(* Logix 5000 project; controller AMCI_3601_AOP_AOI_Sample_RSLogix_V28 vendor 1 type 14 code 108 rev 28.11; software revision 28.00; part 2 of 4 *)

ADD_ON_INSTRUCTION AMCI_3601_AOP_Immediate_Stop   (* revision 0.0, vendor AMCI, ExecuteEnableInFalse *)
// Revision note:
// 3/2020: Version 0 is the initial release
VAR_INPUT
   Axis_Status_Bits : INT; {required}
END_VAR
VAR_OUTPUT
   EN : BOOL; {access Read Only, visible}
   ER : BOOL; {access Read Only, visible}
END_VAR
VAR_IN_OUT
   AMCI_3601_output_data : AM:1769_3601:O:0; {required}
END_VAR
VAR
   Upper_Result_X_1000 : DINT;
   command_data_block : INT[10];
        [1]   // Command Bits LSW
        [3]   // Lower Target Position
        [5]   // Lower Programmed Speed
        [0]   // Command Bits MSW
        [2]   // Upper Target Position
        [4]   // Upper Programmed Speed
END_VAR

ROUTINE EnableInFalse   (* ladder *)
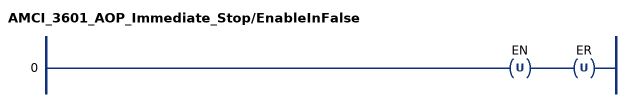
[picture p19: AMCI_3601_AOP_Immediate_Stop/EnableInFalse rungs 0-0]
   0: OTU(EN)OTU(ER);
END_ROUTINE

ROUTINE Logic   (* ladder *)
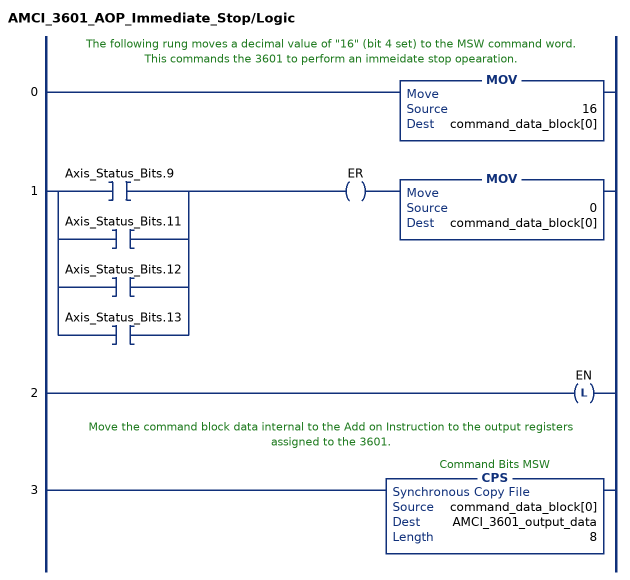
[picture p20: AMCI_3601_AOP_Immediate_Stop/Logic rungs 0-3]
   // The following rung moves a decimal value of "16" (bit 4 set) to the MSW command word.  This commands the 3601 to perform an immeidate stop opearation.
   0: MOV(16,command_data_block[0]);
   1: [XIC(Axis_Status_Bits.9) ,XIC(Axis_Status_Bits.11) ,XIC(Axis_Status_Bits.12) ,XIC(Axis_Status_Bits.13) ]OTE(ER)MOV(0,command_data_block[0]);
   2: OTL(EN);
   // Move the command block data internal to the Add on Instruction to the output registers assigned to the 3601.
   3: CPS(command_data_block[0],AMCI_3601_output_data,8);
END_ROUTINE
END_ADD_ON_INSTRUCTION

ADD_ON_INSTRUCTION AMCI_3601_AOP_Manual_Move_CCW   (* revision 0.0, vendor AMCI, ExecuteEnableInFalse *)
// Revision note:
// 3/2020: Version 0 is the initial release
VAR_INPUT
   Axis_Status_Bits : INT; {required}
   _0_normal_1_S_Curve_Acceleration : BOOL;
   _0_Triangular_1_Trapezoidal_S_Curve : BOOL;
   Programmed_Speed : DINT; {required}
   Acceleration : INT; {required}
   Deceleration : INT; {required}
END_VAR
VAR_OUTPUT
   EN : BOOL; {access Read Only, visible}
   Manual_Move_CCW_Occurring : BOOL; {access Read Only, visible}
   ER : BOOL; {access Read Only, visible}
END_VAR
VAR_IN_OUT
   AMCI_3601_output_data : AM:1769_3601:O:0; {required}
END_VAR
VAR
   Upper_Result_X_1000 : DINT;
   command_data_block : INT[10];
        [1]   // Command Bits LSW
        [3]   // Lower Target Position
        [5]   // Lower Programmed Speed
        [0]   // Command Bits MSW
        [2]   // Upper Target Position
        [4]   // Upper Programmed Speed
END_VAR

ROUTINE EnableInFalse   (* ladder *)
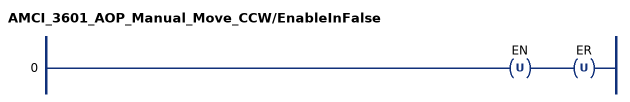
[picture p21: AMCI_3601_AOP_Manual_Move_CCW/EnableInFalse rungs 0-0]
   0: OTU(EN)OTU(ER);
END_ROUTINE

ROUTINE Logic   (* ladder *)
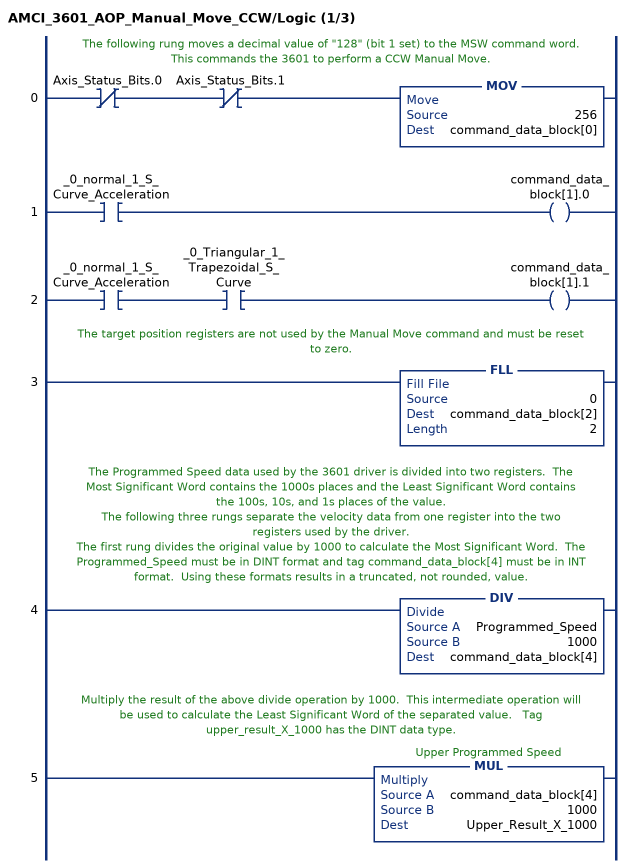
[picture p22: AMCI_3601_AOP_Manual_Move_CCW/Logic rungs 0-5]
   // The following rung moves a decimal value of "128" (bit 1 set) to the MSW command word.  This commands the 3601 to perform a CCW Manual Move.
   0: XIO(Axis_Status_Bits.0)XIO(Axis_Status_Bits.1)MOV(256,command_data_block[0]);
   1: XIC(_0_normal_1_S_Curve_Acceleration)OTE(command_data_block[1].0);
   2: XIC(_0_normal_1_S_Curve_Acceleration)XIC(_0_Triangular_1_Trapezoidal_S_Curve)OTE(command_data_block[1].1);
   // The target position registers are not used by the Manual Move command and must be reset to zero.
   3: FLL(0,command_data_block[2],2);
   // The Programmed Speed data used by the 3601 driver is divided into two registers.  The Most Significant Word contains the 1000s places and the Least Significant Word contains the 100s, 10s, and 1s places of the value.
   // The following three rungs separate the velocity data from one register into the two registers used by the driver.
   // The first rung divides the original value by 1000 to calculate the Most Significant Word.  The Programmed_Speed must be in DINT format and tag command_data_block[4] must be in INT format.  Using these formats results in a truncated, not rounded, value.
   4: DIV(Programmed_Speed,1000,command_data_block[4]);
   // Multiply the result of the above divide operation by 1000.  This intermediate operation will be used to calculate the Least Significant Word of the separated value.   Tag upper_result_X_1000 has the DINT data type.
   5: MUL(command_data_block[4],1000,Upper_Result_X_1000);
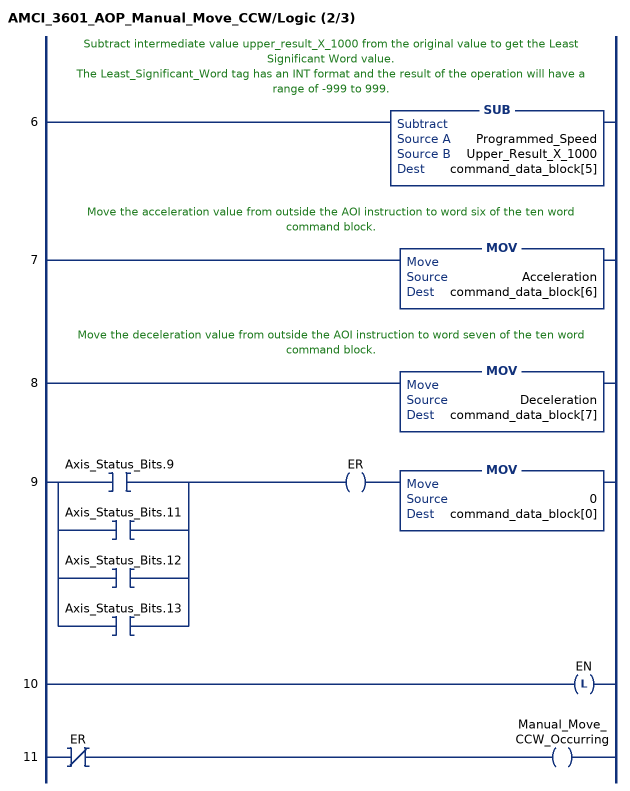
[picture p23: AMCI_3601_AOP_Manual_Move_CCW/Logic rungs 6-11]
   // Subtract intermediate value upper_result_X_1000 from the original value to get the Least Significant Word value.
   // The Least_Significant_Word tag has an INT format and the result of the operation will have a range of -999 to 999.
   6: SUB(Programmed_Speed,Upper_Result_X_1000,command_data_block[5]);
   // Move the acceleration value from outside the AOI instruction to word six of the ten word command block.
   7: MOV(Acceleration,command_data_block[6]);
   // Move the deceleration value from outside the AOI instruction to word seven of the ten word command block.
   8: MOV(Deceleration,command_data_block[7]);
   9: [XIC(Axis_Status_Bits.9) ,XIC(Axis_Status_Bits.11) ,XIC(Axis_Status_Bits.12) ,XIC(Axis_Status_Bits.13) ]OTE(ER)MOV(0,command_data_block[0]);
   10: OTL(EN);
   11: XIO(ER)OTE(Manual_Move_CCW_Occurring);
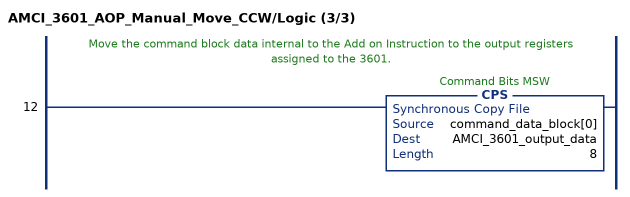
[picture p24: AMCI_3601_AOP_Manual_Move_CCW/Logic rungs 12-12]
   // Move the command block data internal to the Add on Instruction to the output registers assigned to the 3601.
   12: CPS(command_data_block[0],AMCI_3601_output_data,8);
END_ROUTINE
END_ADD_ON_INSTRUCTION

ADD_ON_INSTRUCTION AMCI_3601_AOP_Manual_Move_CW   (* revision 0.0, vendor AMCI, ExecuteEnableInFalse *)
// Revision note:
// 3/2020: Version 0 is the initial release
VAR_INPUT
   Axis_Status_Bits : INT; {required}
   _0_normal_1_S_Curve_Acceleration : BOOL;
   _0_Triangular_1_Trapezoidal_S_Curve : BOOL;
   Programmed_Speed : DINT; {required}
   Acceleration : INT; {required}
   Deceleration : INT; {required}
END_VAR
VAR_OUTPUT
   EN : BOOL; {access Read Only, visible}
   Manual_Move_CW_Occurring : BOOL; {access Read Only, visible}
   ER : BOOL; {access Read Only, visible}
END_VAR
VAR_IN_OUT
   AMCI_3601_output_data : AM:1769_3601:O:0; {required}
END_VAR
VAR
   Upper_Result_X_1000 : DINT;
   command_data_block : INT[10];
        [1]   // Command Bits LSW
        [3]   // Lower Target Position
        [5]   // Lower Programmed Speed
        [0]   // Command Bits MSW
        [2]   // Upper Target Position
        [4]   // Upper Programmed Speed
END_VAR

ROUTINE EnableInFalse   (* ladder *)
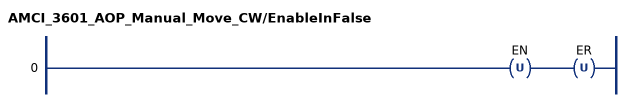
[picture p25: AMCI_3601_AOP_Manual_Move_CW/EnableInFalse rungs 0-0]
   0: OTU(EN)OTU(ER);
END_ROUTINE

ROUTINE Logic   (* ladder *)
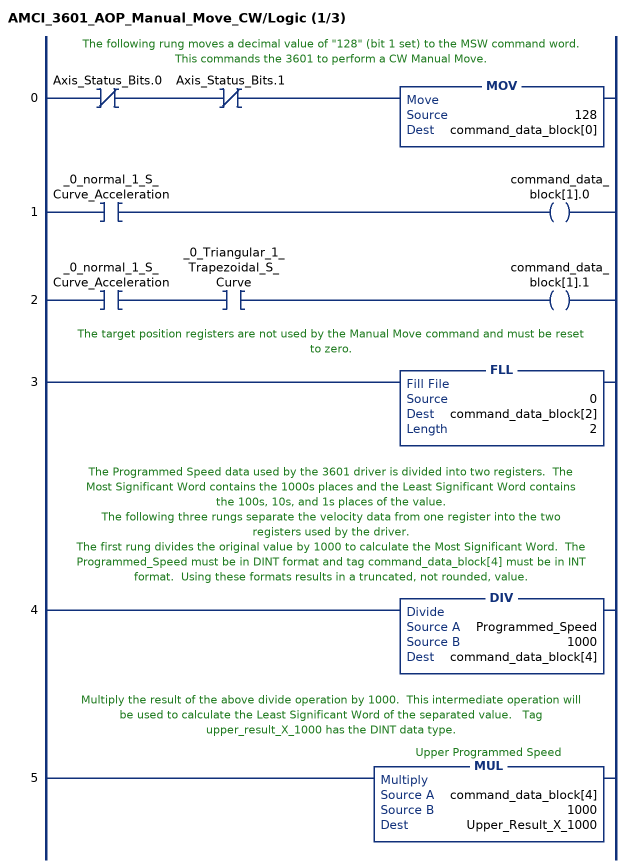
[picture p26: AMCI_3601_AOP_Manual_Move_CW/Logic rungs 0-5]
   // The following rung moves a decimal value of "128" (bit 1 set) to the MSW command word.  This commands the 3601 to perform a CW Manual Move.
   0: XIO(Axis_Status_Bits.0)XIO(Axis_Status_Bits.1)MOV(128,command_data_block[0]);
   1: XIC(_0_normal_1_S_Curve_Acceleration)OTE(command_data_block[1].0);
   2: XIC(_0_normal_1_S_Curve_Acceleration)XIC(_0_Triangular_1_Trapezoidal_S_Curve)OTE(command_data_block[1].1);
   // The target position registers are not used by the Manual Move command and must be reset to zero.
   3: FLL(0,command_data_block[2],2);
   // The Programmed Speed data used by the 3601 driver is divided into two registers.  The Most Significant Word contains the 1000s places and the Least Significant Word contains the 100s, 10s, and 1s places of the value.
   // The following three rungs separate the velocity data from one register into the two registers used by the driver.
   // The first rung divides the original value by 1000 to calculate the Most Significant Word.  The Programmed_Speed must be in DINT format and tag command_data_block[4] must be in INT format.  Using these formats results in a truncated, not rounded, value.
   4: DIV(Programmed_Speed,1000,command_data_block[4]);
   // Multiply the result of the above divide operation by 1000.  This intermediate operation will be used to calculate the Least Significant Word of the separated value.   Tag upper_result_X_1000 has the DINT data type.
   5: MUL(command_data_block[4],1000,Upper_Result_X_1000);
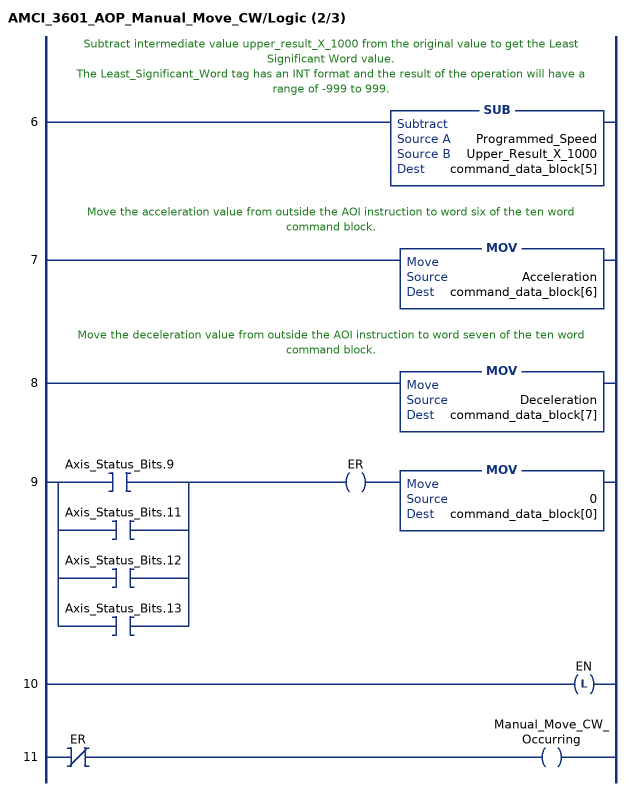
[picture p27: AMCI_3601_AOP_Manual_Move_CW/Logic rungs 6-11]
   // Subtract intermediate value upper_result_X_1000 from the original value to get the Least Significant Word value.
   // The Least_Significant_Word tag has an INT format and the result of the operation will have a range of -999 to 999.
   6: SUB(Programmed_Speed,Upper_Result_X_1000,command_data_block[5]);
   // Move the acceleration value from outside the AOI instruction to word six of the ten word command block.
   7: MOV(Acceleration,command_data_block[6]);
   // Move the deceleration value from outside the AOI instruction to word seven of the ten word command block.
   8: MOV(Deceleration,command_data_block[7]);
   9: [XIC(Axis_Status_Bits.9) ,XIC(Axis_Status_Bits.11) ,XIC(Axis_Status_Bits.12) ,XIC(Axis_Status_Bits.13) ]OTE(ER)MOV(0,command_data_block[0]);
   10: OTL(EN);
   11: XIO(ER)OTE(Manual_Move_CW_Occurring);
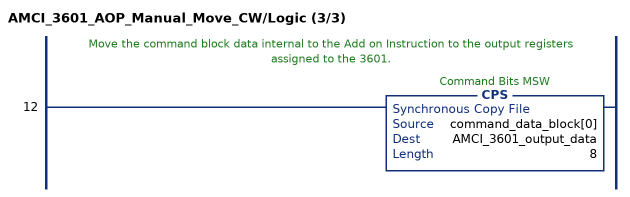
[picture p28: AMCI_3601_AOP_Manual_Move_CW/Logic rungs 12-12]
   // Move the command block data internal to the Add on Instruction to the output registers assigned to the 3601.
   12: CPS(command_data_block[0],AMCI_3601_output_data,8);
END_ROUTINE
END_ADD_ON_INSTRUCTION

ADD_ON_INSTRUCTION AMCI_3601_AOP_Min_Registration_Distance   (* revision 0.0, vendor AMCI, ExecuteEnableInFalse *)
// Revision note:
// 3/2020: Version 0 is the initial release
VAR_INPUT
   Axis_Status_Bits : INT; {required}
   Target_Position : DINT; {required}
END_VAR
VAR_OUTPUT
   EN : BOOL; {access Read Only, visible}
   ER : BOOL; {access Read Only, visible}
END_VAR
VAR_IN_OUT
   AMCI_3601_output_data : AM:1769_3601:O:0; {required}
END_VAR
VAR
   Upper_Result_X_1000 : DINT;
   command_data_block : INT[10];
        [1]   // Command Bits LSW
        [3]   // Lower Target Position
        [5]   // Lower Programmed Speed
        [0]   // Command Bits MSW
        [2]   // Upper Target Position
        [4]   // Upper Programmed Speed
END_VAR

ROUTINE EnableInFalse   (* ladder *)
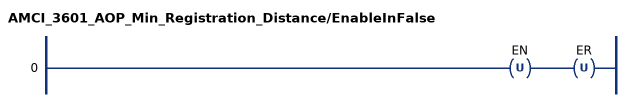
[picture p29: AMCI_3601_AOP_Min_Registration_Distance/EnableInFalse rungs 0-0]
   0: OTU(EN)OTU(ER);
END_ROUTINE

ROUTINE Logic   (* ladder *)
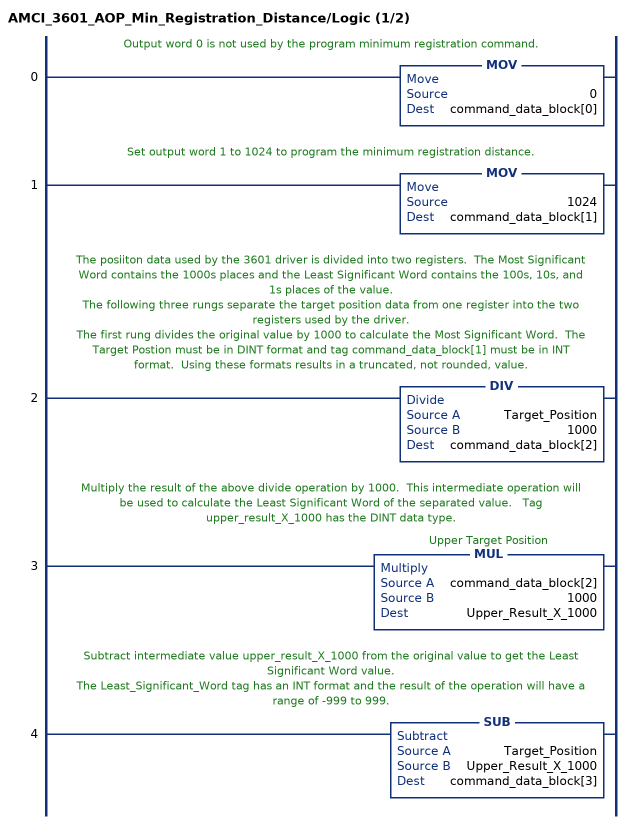
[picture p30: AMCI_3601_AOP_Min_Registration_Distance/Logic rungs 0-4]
   // Output word 0 is not used by the program minimum registration command.
   0: MOV(0,command_data_block[0]);
   // Set output word 1 to 1024 to program the minimum registration distance.
   1: MOV(1024,command_data_block[1]);
   // The posiiton data used by the 3601 driver is divided into two registers.  The Most Significant Word contains the 1000s places and the Least Significant Word contains the 100s, 10s, and 1s places of the value.
   // The following three rungs separate the target position data from one register into the two registers used by the driver.
   // The first rung divides the original value by 1000 to calculate the Most Significant Word.  The Target Postion must be in DINT format and tag command_data_block[1] must be in INT format.  Using these formats results in a truncated, not rounded, value.
   2: DIV(Target_Position,1000,command_data_block[2]);
   // Multiply the result of the above divide operation by 1000.  This intermediate operation will be used to calculate the Least Significant Word of the separated value.   Tag upper_result_X_1000 has the DINT data type.
   3: MUL(command_data_block[2],1000,Upper_Result_X_1000);
   // Subtract intermediate value upper_result_X_1000 from the original value to get the Least Significant Word value.
   // The Least_Significant_Word tag has an INT format and the result of the operation will have a range of -999 to 999.
   4: SUB(Target_Position,Upper_Result_X_1000,command_data_block[3]);
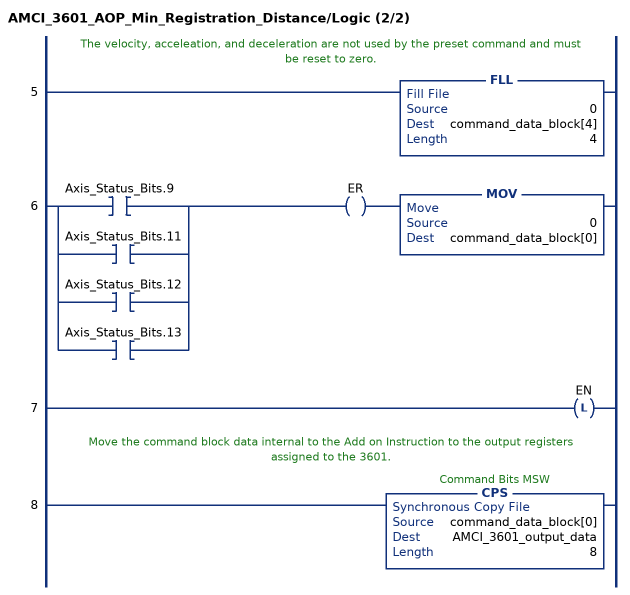
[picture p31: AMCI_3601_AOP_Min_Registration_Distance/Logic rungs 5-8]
   // The velocity, acceleation, and deceleration are not used by the preset command and must be reset to zero.
   5: FLL(0,command_data_block[4],4);
   6: [XIC(Axis_Status_Bits.9) ,XIC(Axis_Status_Bits.11) ,XIC(Axis_Status_Bits.12) ,XIC(Axis_Status_Bits.13) ]OTE(ER)MOV(0,command_data_block[0]);
   7: OTL(EN);
   // Move the command block data internal to the Add on Instruction to the output registers assigned to the 3601.
   8: CPS(command_data_block[0],AMCI_3601_output_data,8);
END_ROUTINE
END_ADD_ON_INSTRUCTION

ADD_ON_INSTRUCTION AMCI_3601_AOP_Preset   (* revision 0.0, vendor AMCI, ExecuteEnableInFalse *)
// Revision note:
// 3/2020: Version 0 is the initial release
VAR_INPUT
   Axis_Status_Bits : INT; {required}
   Target_Position : DINT; {required}
END_VAR
VAR_OUTPUT
   EN : BOOL; {access Read Only, visible}
   ER : BOOL; {access Read Only, visible}
END_VAR
VAR_IN_OUT
   AMCI_3601_output_data : AM:1769_3601:O:0; {required}
END_VAR
VAR
   Upper_Result_X_1000 : DINT;
   command_data_block : INT[10];
        [1]   // Command Bits LSW
        [3]   // Lower Target Position
        [5]   // Lower Programmed Speed
        [0]   // Command Bits MSW
        [2]   // Upper Target Position
        [4]   // Upper Programmed Speed
END_VAR

ROUTINE EnableInFalse   (* ladder *)
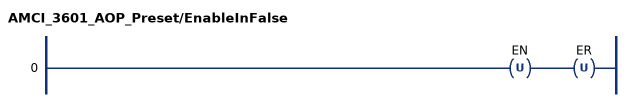
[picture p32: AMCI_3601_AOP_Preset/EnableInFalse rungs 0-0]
   0: OTU(EN)OTU(ER);
END_ROUTINE

ROUTINE Logic   (* ladder *)
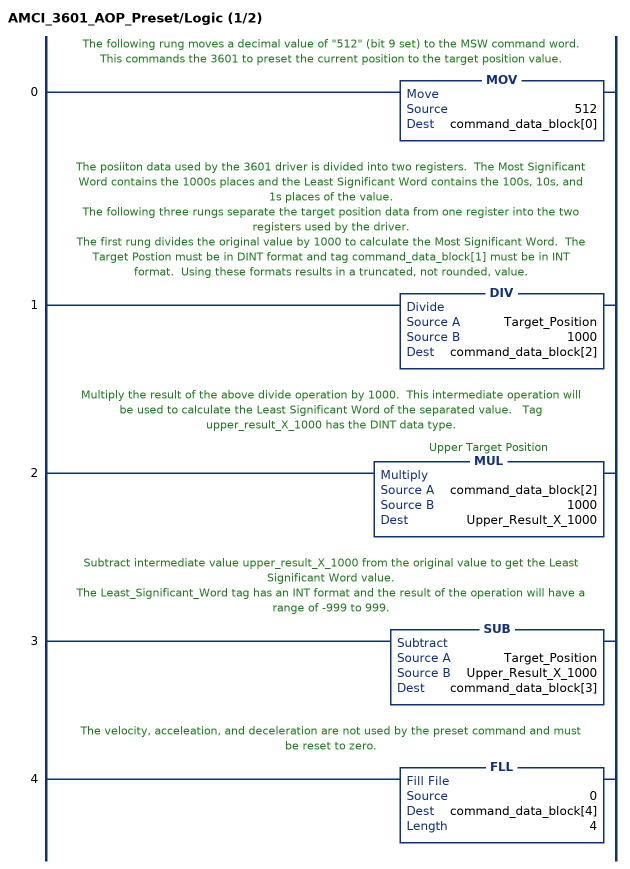
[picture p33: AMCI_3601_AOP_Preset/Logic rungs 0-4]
   // The following rung moves a decimal value of "512" (bit 9 set) to the MSW command word.  This commands the 3601 to preset the current position to the target position value.
   0: MOV(512,command_data_block[0]);
   // The posiiton data used by the 3601 driver is divided into two registers.  The Most Significant Word contains the 1000s places and the Least Significant Word contains the 100s, 10s, and 1s places of the value.
   // The following three rungs separate the target position data from one register into the two registers used by the driver.
   // The first rung divides the original value by 1000 to calculate the Most Significant Word.  The Target Postion must be in DINT format and tag command_data_block[1] must be in INT format.  Using these formats results in a truncated, not rounded, value.
   1: DIV(Target_Position,1000,command_data_block[2]);
   // Multiply the result of the above divide operation by 1000.  This intermediate operation will be used to calculate the Least Significant Word of the separated value.   Tag upper_result_X_1000 has the DINT data type.
   2: MUL(command_data_block[2],1000,Upper_Result_X_1000);
   // Subtract intermediate value upper_result_X_1000 from the original value to get the Least Significant Word value.
   // The Least_Significant_Word tag has an INT format and the result of the operation will have a range of -999 to 999.
   3: SUB(Target_Position,Upper_Result_X_1000,command_data_block[3]);
   // The velocity, acceleation, and deceleration are not used by the preset command and must be reset to zero.
   4: FLL(0,command_data_block[4],4);
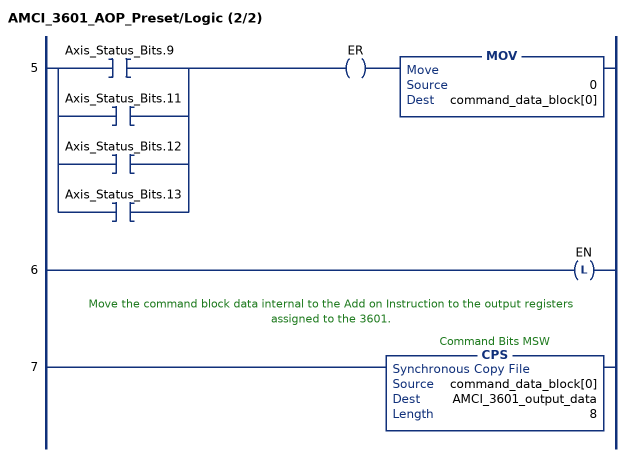
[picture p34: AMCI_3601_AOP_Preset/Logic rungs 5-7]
   5: [XIC(Axis_Status_Bits.9) ,XIC(Axis_Status_Bits.11) ,XIC(Axis_Status_Bits.12) ,XIC(Axis_Status_Bits.13) ]OTE(ER)MOV(0,command_data_block[0]);
   6: OTL(EN);
   // Move the command block data internal to the Add on Instruction to the output registers assigned to the 3601.
   7: CPS(command_data_block[0],AMCI_3601_output_data,8);
END_ROUTINE
END_ADD_ON_INSTRUCTION

ADD_ON_INSTRUCTION AMCI_3601_AOP_Preset_Encoder   (* revision 0.0, vendor AMCI, ExecuteEnableInFalse *)
// Revision note:
// 3/2020: Version 0 is the initial release
VAR_INPUT
   Axis_Status_Bits : INT; {required}
   Target_Position : DINT; {required}
END_VAR
VAR_OUTPUT
   EN : BOOL; {access Read Only, visible}
   ER : BOOL; {access Read Only, visible}
END_VAR
VAR_IN_OUT
   AMCI_3601_output_data : AM:1769_3601:O:0; {required}
END_VAR
VAR
   Upper_Result_X_1000 : DINT;
   command_data_block : INT[10];
        [1]   // Command Bits LSW
        [3]   // Lower Target Position
        [5]   // Lower Programmed Speed
        [0]   // Command Bits MSW
        [2]   // Upper Target Position
        [4]   // Upper Programmed Speed
END_VAR

ROUTINE EnableInFalse   (* ladder *)
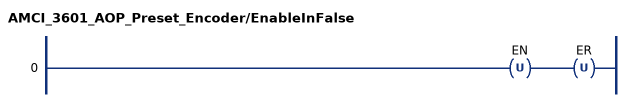
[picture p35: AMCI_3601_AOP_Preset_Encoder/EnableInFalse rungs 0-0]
   0: OTU(EN)OTU(ER);
END_ROUTINE

ROUTINE Logic   (* ladder *)
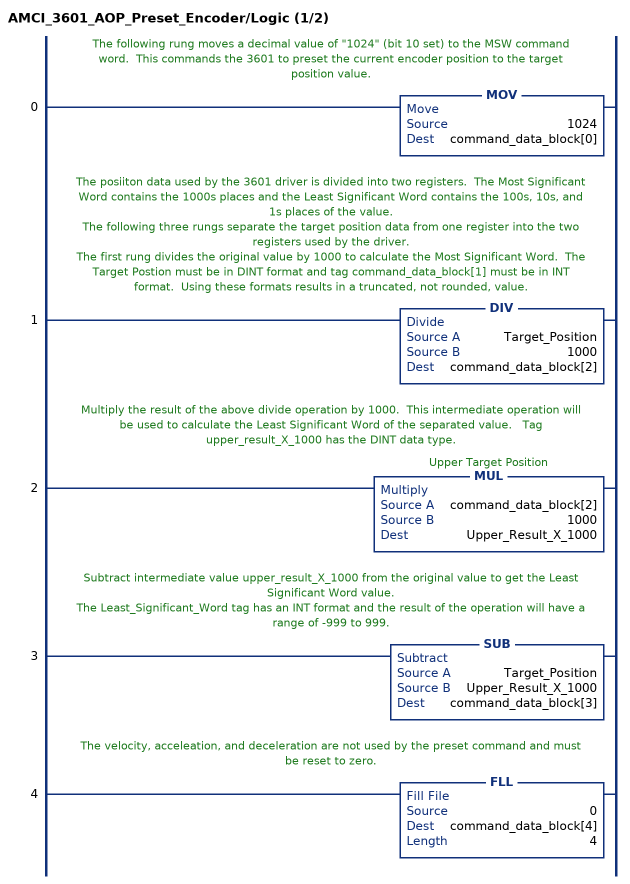
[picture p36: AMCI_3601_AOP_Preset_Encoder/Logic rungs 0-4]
   // The following rung moves a decimal value of "1024" (bit 10 set) to the MSW command word.  This commands the 3601 to preset the current encoder position to the target position value.
   0: MOV(1024,command_data_block[0]);
   // The posiiton data used by the 3601 driver is divided into two registers.  The Most Significant Word contains the 1000s places and the Least Significant Word contains the 100s, 10s, and 1s places of the value.
   // The following three rungs separate the target position data from one register into the two registers used by the driver.
   // The first rung divides the original value by 1000 to calculate the Most Significant Word.  The Target Postion must be in DINT format and tag command_data_block[1] must be in INT format.  Using these formats results in a truncated, not rounded, value.
   1: DIV(Target_Position,1000,command_data_block[2]);
   // Multiply the result of the above divide operation by 1000.  This intermediate operation will be used to calculate the Least Significant Word of the separated value.   Tag upper_result_X_1000 has the DINT data type.
   2: MUL(command_data_block[2],1000,Upper_Result_X_1000);
   // Subtract intermediate value upper_result_X_1000 from the original value to get the Least Significant Word value.
   // The Least_Significant_Word tag has an INT format and the result of the operation will have a range of -999 to 999.
   3: SUB(Target_Position,Upper_Result_X_1000,command_data_block[3]);
   // The velocity, acceleation, and deceleration are not used by the preset command and must be reset to zero.
   4: FLL(0,command_data_block[4],4);
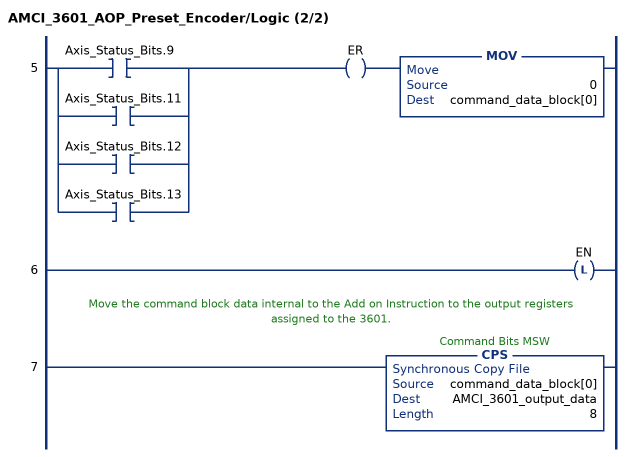
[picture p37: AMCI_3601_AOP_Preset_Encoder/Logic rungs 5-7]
   5: [XIC(Axis_Status_Bits.9) ,XIC(Axis_Status_Bits.11) ,XIC(Axis_Status_Bits.12) ,XIC(Axis_Status_Bits.13) ]OTE(ER)MOV(0,command_data_block[0]);
   6: OTL(EN);
   // Move the command block data internal to the Add on Instruction to the output registers assigned to the 3601.
   7: CPS(command_data_block[0],AMCI_3601_output_data,8);
END_ROUTINE
END_ADD_ON_INSTRUCTION
